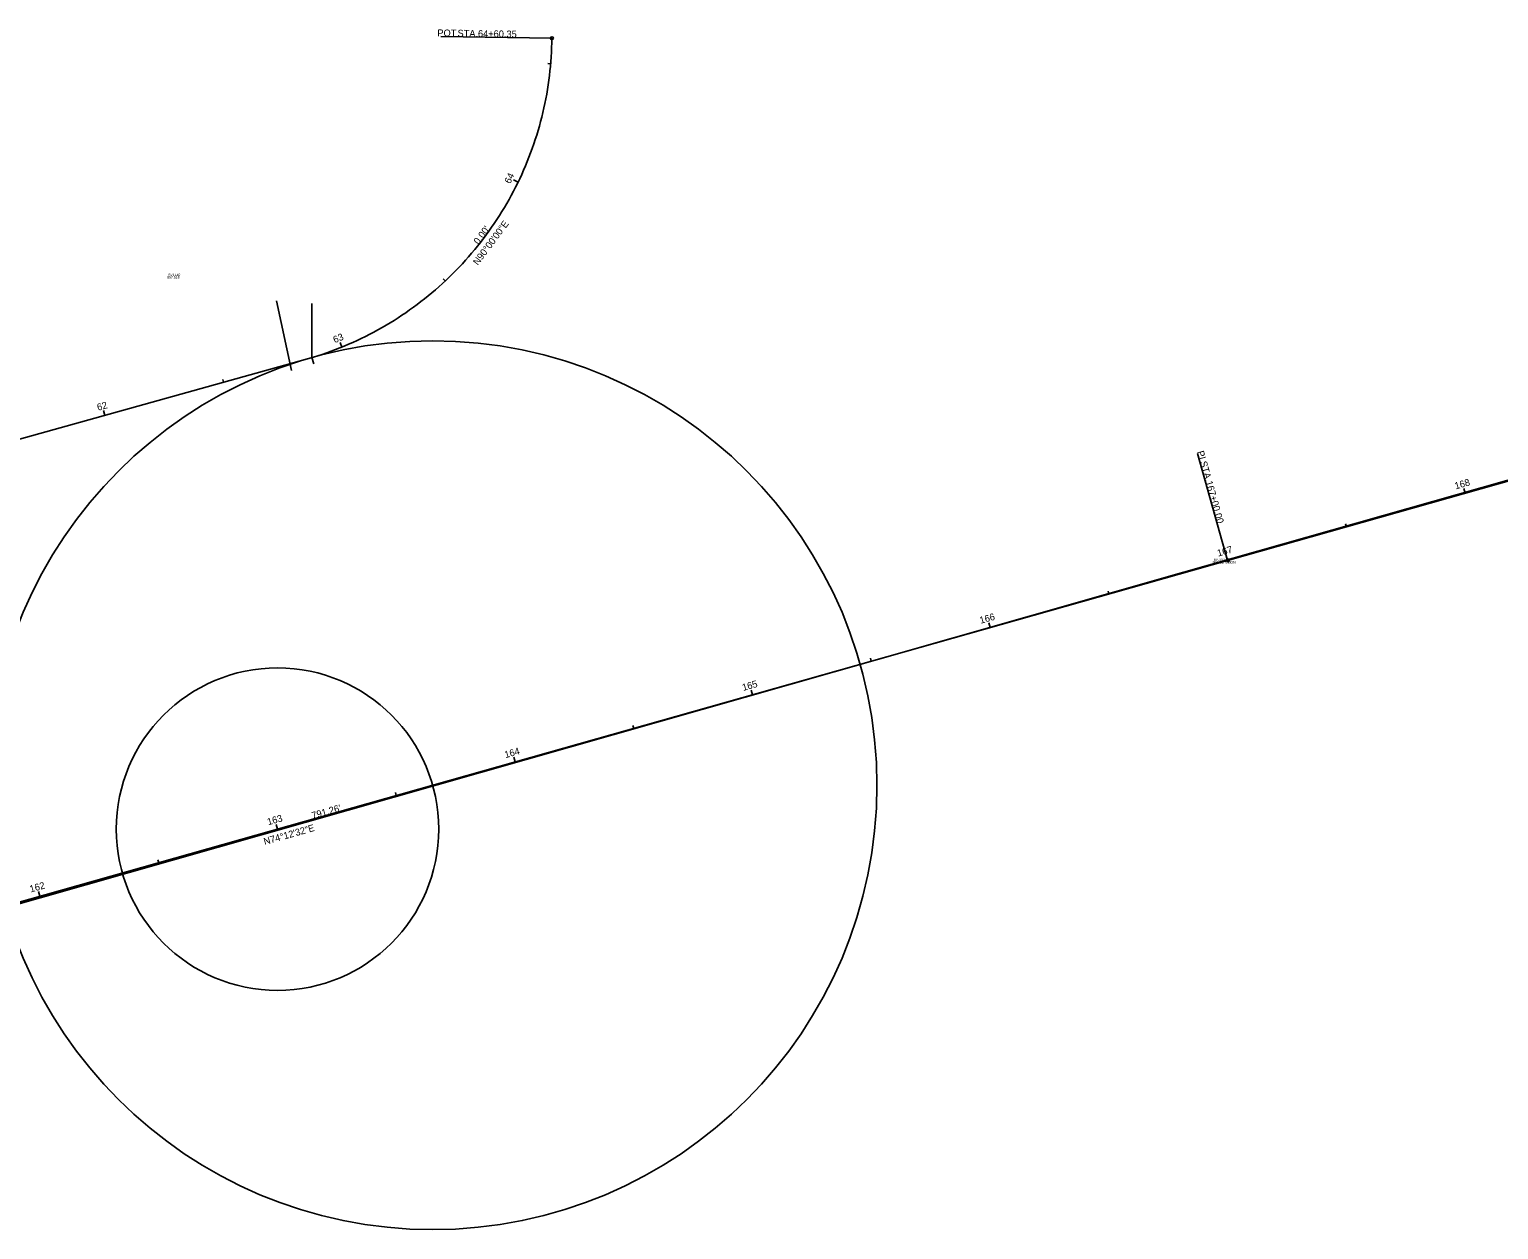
# Model space of a CAD drawing. Extents: x 2272920 to 2277360, y 743591 to 745058.
# Drawn here: x 2276197 to 2276793, y 744138 to 744624 of the extents above; entities that cross this region are included whole.
import ezdxf

# ---------------------------------------------------------------- set-up
doc = ezdxf.new("R2010")
doc.units = 0
for name, color, linetype in [('GE_X_Alignment', 7, 'Continuous'), ('GE_X_Alignment_100_Bearings', 7, 'Continuous'), ('GE_X_Alignment_100_Cardinal_Points', 7, 'Continuous'), ('GE_X_Alignment_100_Distances', 7, 'Continuous'), ('GE_X_Alignment_100_Stations', 7, 'Continuous'), ('SC_Scratch1', 7, 'Continuous'), ('SC_Scratch3', 7, 'Continuous'), ('SV_X_Text_Comment', 7, 'Continuous'), ('SV_X_Text_Elevation', 7, 'Continuous'), ('SV_X_Text_Name', 7, 'Continuous')]:
    doc.layers.add(name, color=color, linetype=linetype)

msp = doc.modelspace()

# ---------------------------------------------------------------- linework, layer by layer
at = {"layer": 'GE_X_Alignment'}
for p, q in [((2276682.83, 744409.06), (2277356.39, 744599.64)), ((2275811.23, 744351.63), (2276312.44, 744491.37)), ((2275921.44, 744193.73), (2276682.83, 744409.06))]:
    msp.add_line(p, q, dxfattribs=at)
msp.add_lwpolyline([(2276312.44, 744491.37), (2276314.26, 744491.93), (2276316.06, 744492.52), (2276317.85, 744493.14), (2276319.64, 744493.78), (2276321.41, 744494.45), (2276323.18, 744495.14), (2276324.94, 744495.85), (2276326.68, 744496.59), (2276328.42, 744497.35), (2276330.15, 744498.14), (2276331.86, 744498.95), (2276333.56, 744499.79), (2276335.26, 744500.64), (2276336.93, 744501.53), (2276338.6, 744502.43), (2276340.26, 744503.36), (2276341.9, 744504.31), (2276343.52, 744505.29), (2276345.14, 744506.28), (2276346.74, 744507.3), (2276348.32, 744508.34), (2276349.9, 744509.4), (2276351.45, 744510.49), (2276352.99, 744511.6), (2276354.52, 744512.72), (2276356.03, 744513.87), (2276357.52, 744515.04), (2276359, 744516.23), (2276360.46, 744517.44), (2276361.9, 744518.67), (2276363.33, 744519.92), (2276364.74, 744521.19), (2276366.13, 744522.48), (2276367.5, 744523.79), (2276368.85, 744525.12), (2276370.19, 744526.47), (2276371.51, 744527.83), (2276372.8, 744529.22), (2276374.08, 744530.62), (2276375.34, 744532.04), (2276376.58, 744533.47), (2276377.8, 744534.93), (2276379, 744536.4), (2276380.17, 744537.88), (2276381.33, 744539.39), (2276382.47, 744540.9), (2276383.58, 744542.44), (2276384.68, 744543.99), (2276385.75, 744545.55), (2276386.8, 744547.13), (2276387.83, 744548.73), (2276388.83, 744550.34), (2276389.82, 744551.96), (2276390.78, 744553.59), (2276391.71, 744555.24), (2276392.63, 744556.9), (2276393.52, 744558.58), (2276394.39, 744560.26), (2276395.23, 744561.96), (2276396.05, 744563.67), (2276396.85, 744565.39), (2276397.62, 744567.13), (2276398.37, 744568.87), (2276399.1, 744570.62), (2276399.8, 744572.38), (2276400.47, 744574.16), (2276401.12, 744575.94), (2276401.75, 744577.73), (2276402.35, 744579.53), (2276402.93, 744581.34), (2276403.48, 744583.15), (2276404, 744584.97), (2276404.5, 744586.8), (2276404.98, 744588.64), (2276405.43, 744590.48), (2276405.85, 744592.33), (2276406.25, 744594.19), (2276406.62, 744596.05), (2276406.97, 744597.91), (2276407.29, 744599.78), (2276407.58, 744601.65), (2276407.85, 744603.53), (2276408.09, 744605.41), (2276408.31, 744607.3), (2276408.49, 744609.18), (2276408.66, 744611.07), (2276408.79, 744612.97), (2276408.9, 744614.86), (2276408.99, 744616.75), (2276409.05, 744618.65), (2276409.08, 744620.55)], dxfattribs=at)
at = {"layer": 'GE_X_Alignment_100_Cardinal_Points'}
for p, q in [((2276409.08, 744620.55), (2276364.08, 744621.29)), ((2276682.83, 744409.06), (2276670.58, 744452.36))]:
    msp.add_line(p, q, dxfattribs=at)
for centre in [(2276409.08, 744620.55), (2276682.83, 744409.06)]:
    msp.add_circle(centre, 0.6, dxfattribs=at)
at = {"layer": 'GE_X_Alignment_100_Stations'}
for p, q in [((2276408.58, 744610.21), (2276407.39, 744610.31)), ((2276395.38, 744562.27), (2276393.58, 744563.14)), ((2276365.88, 744522.25), (2276365.06, 744523.13)), ((2276323.99, 744495.47), (2276323.24, 744497.32)), ((2276276.09, 744481.23), (2276275.77, 744482.39)), ((2276227.93, 744467.8), (2276227.39, 744469.73)), ((2276779.05, 744436.28), (2276778.51, 744438.21)), ((2276730.94, 744422.67), (2276730.61, 744423.82)), ((2276682.83, 744409.06), (2276682.29, 744410.98)), ((2276634.72, 744395.45), (2276634.39, 744396.6)), ((2276586.6, 744381.84), (2276586.06, 744383.77)), ((2276538.49, 744368.24), (2276538.16, 744369.39)), ((2276490.38, 744354.63), (2276489.83, 744356.55)), ((2276442.26, 744341.02), (2276441.94, 744342.18)), ((2276394.15, 744327.42), (2276393.61, 744329.34)), ((2276346.04, 744313.81), (2276345.71, 744314.97)), ((2276297.93, 744300.2), (2276297.38, 744302.13)), ((2276249.81, 744286.6), (2276249.49, 744287.75)), ((2276201.7, 744272.99), (2276201.15, 744274.92))]:
    msp.add_line(p, q, dxfattribs=at)
at = {"layer": 'SC_Scratch1'}
for p, q in [((2276665.1, 744404.26), (2277338.38, 744595.82)), ((2276541.02, 744368.96), (2276665.1, 744404.26)), ((2276152.08, 744258.3), (2276541.02, 744368.96))]:
    msp.add_line(p, q, dxfattribs=at)
msp.add_lwpolyline([(2276312.44, 744491.37), (2276314.26, 744491.93), (2276316.06, 744492.52), (2276317.85, 744493.14), (2276319.64, 744493.78), (2276321.41, 744494.45), (2276323.18, 744495.14), (2276324.94, 744495.85), (2276326.68, 744496.59), (2276328.42, 744497.35), (2276330.15, 744498.14), (2276331.86, 744498.95), (2276333.56, 744499.79), (2276335.26, 744500.64), (2276336.93, 744501.53), (2276338.6, 744502.43), (2276340.26, 744503.36), (2276341.9, 744504.31), (2276343.52, 744505.29), (2276345.14, 744506.28), (2276346.74, 744507.3), (2276348.32, 744508.34), (2276349.9, 744509.4), (2276351.45, 744510.49), (2276352.99, 744511.6), (2276354.52, 744512.72), (2276356.03, 744513.87), (2276357.52, 744515.04), (2276359, 744516.23), (2276360.46, 744517.44), (2276361.9, 744518.67), (2276363.33, 744519.92), (2276364.74, 744521.19), (2276366.13, 744522.48), (2276367.5, 744523.79), (2276368.85, 744525.12), (2276370.19, 744526.47), (2276371.51, 744527.83), (2276372.8, 744529.22), (2276374.08, 744530.62), (2276375.34, 744532.04), (2276376.58, 744533.47), (2276377.8, 744534.93), (2276379, 744536.4), (2276380.17, 744537.88), (2276381.33, 744539.39), (2276382.47, 744540.9), (2276383.58, 744542.44), (2276384.68, 744543.99), (2276385.75, 744545.55), (2276386.8, 744547.13), (2276387.83, 744548.73), (2276388.83, 744550.34), (2276389.82, 744551.96), (2276390.78, 744553.59), (2276391.71, 744555.24), (2276392.63, 744556.9), (2276393.52, 744558.58), (2276394.39, 744560.26), (2276395.23, 744561.96), (2276396.05, 744563.67), (2276396.85, 744565.39), (2276397.62, 744567.13), (2276398.37, 744568.87), (2276399.1, 744570.62), (2276399.8, 744572.38), (2276400.47, 744574.16), (2276401.12, 744575.94), (2276401.75, 744577.73), (2276402.35, 744579.53), (2276402.93, 744581.34), (2276403.48, 744583.15), (2276404, 744584.97), (2276404.5, 744586.8), (2276404.98, 744588.64), (2276405.43, 744590.48), (2276405.85, 744592.33), (2276406.25, 744594.19), (2276406.62, 744596.05), (2276406.97, 744597.91), (2276407.29, 744599.78), (2276407.58, 744601.65), (2276407.85, 744603.53), (2276408.09, 744605.41), (2276408.31, 744607.3), (2276408.49, 744609.18), (2276408.66, 744611.07), (2276408.79, 744612.97), (2276408.9, 744614.86), (2276408.99, 744616.75), (2276409.05, 744618.65), (2276409.08, 744620.55)], dxfattribs=at)
at = {"layer": 'SC_Scratch3'}
for p, q in [((2276303.57, 744485.93), (2276297.49, 744514.26)), ((2276311.79, 744491.18), (2276311.79, 744513.08))]:
    msp.add_line(p, q, dxfattribs=at)
msp.add_lwpolyline([(2276311.79, 744491.18), (2276311.79, 744491.18), (2276312.66, 744488.62)], dxfattribs=at)
for centre, radius in [((2276360.77, 744317.98), 180), ((2276297.93, 744300.2), 65.31)]:
    msp.add_circle(centre, radius, dxfattribs=at)

# ---------------------------------------------------------------- texts
at = {"layer": 'GE_X_Alignment_100_Bearings'}
for s, rotation, p in [('N90°00\'00"E', 53.2017, (2276379.08, 744528.37)), ('N74°12\'32"E', 15.79111, (2276292.74, 744293.75))]:
    msp.add_text(s, height=2.8, rotation=rotation, dxfattribs=at).set_placement(p)
at = {"layer": 'GE_X_Alignment_100_Cardinal_Points'}
for s, rotation, p in [('POT', 359.05108, (2276362.66, 744621.35)), (' STA. ', 359.05108, (2276369.79, 744621.23)), ('64+60.35', 359.05108, (2276379.11, 744621.08)), ('PI', 285.79924, (2276670.43, 744453.04)), (' STA. ', 285.79924, (2276671.33, 744449.84)), ('167+00.00', 285.79924, (2276673.87, 744440.87))]:
    msp.add_text(s, height=2.8, rotation=rotation, dxfattribs=at).set_placement(p)
at = {"layer": 'GE_X_Alignment_100_Distances'}
for s, rotation, p in [("0.00'", 53.2017, (2276379.35, 744536.8)), ("791.26'", 15.79111, (2276312.18, 744304.25))]:
    msp.add_text(s, height=2.8, rotation=rotation, dxfattribs=at).set_placement(p)
at = {"layer": 'GE_X_Alignment_100_Stations'}
for s, rotation, p in [('64', 64.35484, (2276392.19, 744561.41)), ('63', 22.13223, (2276321.12, 744497)), ('62', 15.57807, (2276225.24, 744469.65)), ('168', 15.79924, (2276775.24, 744437.8)), ('167', 15.79111, (2276679.03, 744410.58)), ('166', 15.79111, (2276582.79, 744383.36)), ('165', 15.79111, (2276486.61, 744356.16)), ('164', 15.79111, (2276390.31, 744328.93)), ('163', 15.79111, (2276294.17, 744301.74)), ('162', 15.79111, (2276197.93, 744274.52))]:
    msp.add_text(s, height=2.8, rotation=rotation, dxfattribs=at).set_placement(p)
at = {"layer": 'SV_X_Text_Comment'}
msp.add_text('CMON', height=1, dxfattribs=at).set_placement((2276681.85, 744407.78))
at = {"layer": 'SV_X_Text_Elevation'}
for s, p in [('857.518', (2276253.24, 744523.22)), ('903.017', (2276676.76, 744407.78))]:
    msp.add_text(s, height=1, dxfattribs=at).set_placement(p)
at = {"layer": 'SV_X_Text_Name'}
for s, p in [('SV1140', (2276253.63, 744524.22)), ('MN102', (2276677.22, 744408.78))]:
    msp.add_text(s, height=1, dxfattribs=at).set_placement(p)

doc.saveas('drawing.dxf')
